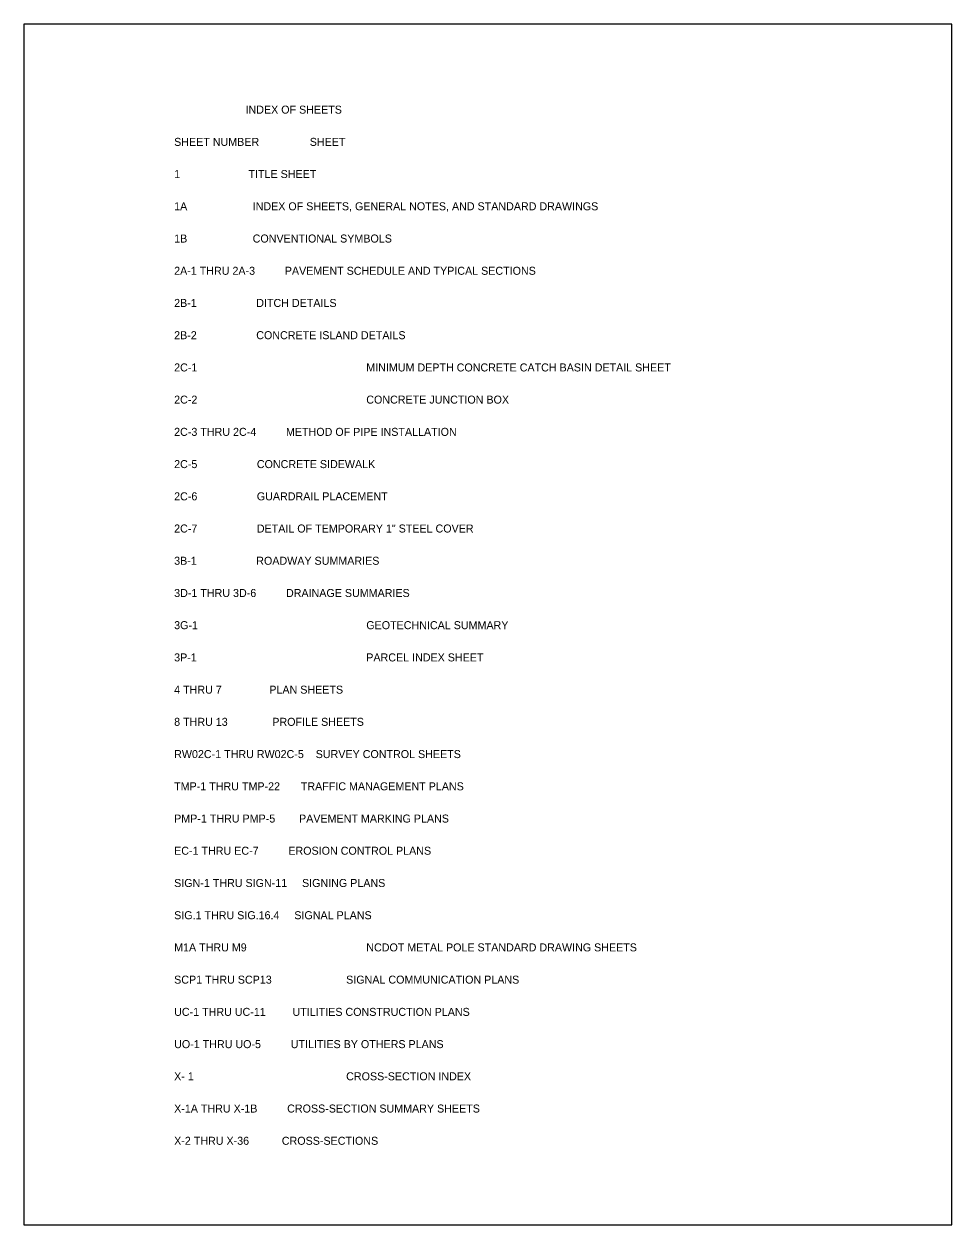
# Model space of a CAD drawing. Extents: x 779200 to 786346, y 600107 to 602297.
# Drawn here: x 779200 to 780475, y 600350 to 602000 of the extents above; entities that cross this region are included whole.
import ezdxf

# ---------------------------------------------------------------- set-up
doc = ezdxf.new("R2010")
doc.units = 0
doc.layers.add('Sheet Sticker Preliminary CELL', color=7, linetype='Continuous')

msp = doc.modelspace()

# ---------------------------------------------------------------- linework, layer by layer
at = {"layer": 'Sheet Sticker Preliminary CELL'}
msp.add_lwpolyline([(779199.8, 600349.7), (780474.8, 600349.7), (780474.8, 601999.7), (779199.8, 601999.7)], close=True, dxfattribs=at)

# ---------------------------------------------------------------- texts
for s, p in [('                        INDEX OF SHEETS ', (779406.1, 601876.6)), ('SHEET NUMBER                 SHEET   ', (779406.1, 601832.3)), ('1                       TITLE SHEET', (779406.1, 601788.1)), ('1A                      INDEX OF SHEETS, GENERAL NOTES, AND STANDARD DRAWINGS', (779406.1, 601743.8)), ('1B                      CONVENTIONAL SYMBOLS ', (779406.1, 601699.5)), ('2A-1 THRU 2A-3          PAVEMENT SCHEDULE AND TYPICAL SECTIONS', (779406.1, 601655.2)), ('2B-1                    DITCH DETAILS', (779406.1, 601611)), ('2B-2                    CONCRETE ISLAND DETAILS', (779406.1, 601566.7)), ('2C-1 ', (779406.1, 601522.4)), ('MINIMUM DEPTH CONCRETE CATCH BASIN DETAIL SHEET', (779670.1, 601522.4)), ('2C-2 ', (779406.1, 601478.2)), ('CONCRETE JUNCTION BOX', (779670.1, 601478.2)), ('2C-3 THRU 2C-4          METHOD OF PIPE INSTALLATION', (779406.1, 601433.9)), ('2C-5                    CONCRETE SIDEWALK', (779406.1, 601389.6)), ('2C-6                    GUARDRAIL PLACEMENT', (779406.1, 601345.3)), ('2C-7                    DETAIL OF TEMPORARY 1" STEEL COVER', (779406.1, 601301.1)), ('3B-1                    ROADWAY SUMMARIES', (779406.1, 601256.8)), ('3D-1 THRU 3D-6          DRAINAGE SUMMARIES', (779406.1, 601212.5)), ('3G-1', (779406.1, 601168.3)), ('GEOTECHNICAL SUMMARY', (779670.1, 601168.3)), ('3P-1                    ', (779406.1, 601124)), ('PARCEL INDEX SHEET', (779670.1, 601124)), ('4 THRU 7                PLAN SHEETS', (779406.1, 601079.7)), ('8 THRU 13               PROFILE SHEETS', (779406.1, 601035.5)), ('RW02C-1 THRU RW02C-5    SURVEY CONTROL SHEETS', (779406.1, 600991.2)), ('TMP-1 THRU TMP-22       TRAFFIC MANAGEMENT PLANS', (779406.1, 600946.9)), ('PMP-1 THRU PMP-5        PAVEMENT MARKING PLANS', (779406.1, 600902.6)), ('EC-1 THRU EC-7          EROSION CONTROL PLANS', (779406.1, 600858.4)), ('SIGN-1 THRU SIGN-11     SIGNING PLANS', (779406.1, 600814.1)), ('SIG.1 THRU SIG.16.4     SIGNAL PLANS', (779406.1, 600769.8)), ('M1A THRU M9      ', (779406.1, 600725.6)), ('NCDOT METAL POLE STANDARD DRAWING SHEETS', (779670.1, 600725.6)), ('SCP1 THRU SCP13', (779406.1, 600681.3)), ('    SIGNAL COMMUNICATION PLANS', (779626.1, 600681.3)), ('UC-1 THRU UC-11         UTILITIES CONSTRUCTION PLANS', (779406.1, 600637)), ('UO-1 THRU UO-5          UTILITIES BY OTHERS PLANS', (779406.1, 600592.7)), ('X- 1', (779406.1, 600548.5)), ('    CROSS-SECTION INDEX', (779626.1, 600548.5)), ('X-1A THRU X-1B          CROSS-SECTION SUMMARY SHEETS', (779406.1, 600504.2)), ('X-2 THRU X-36           CROSS-SECTIONS', (779406.1, 600459.9))]:
    msp.add_text(s, height=11, dxfattribs=at).set_placement(p)

doc.saveas('drawing.dxf')
